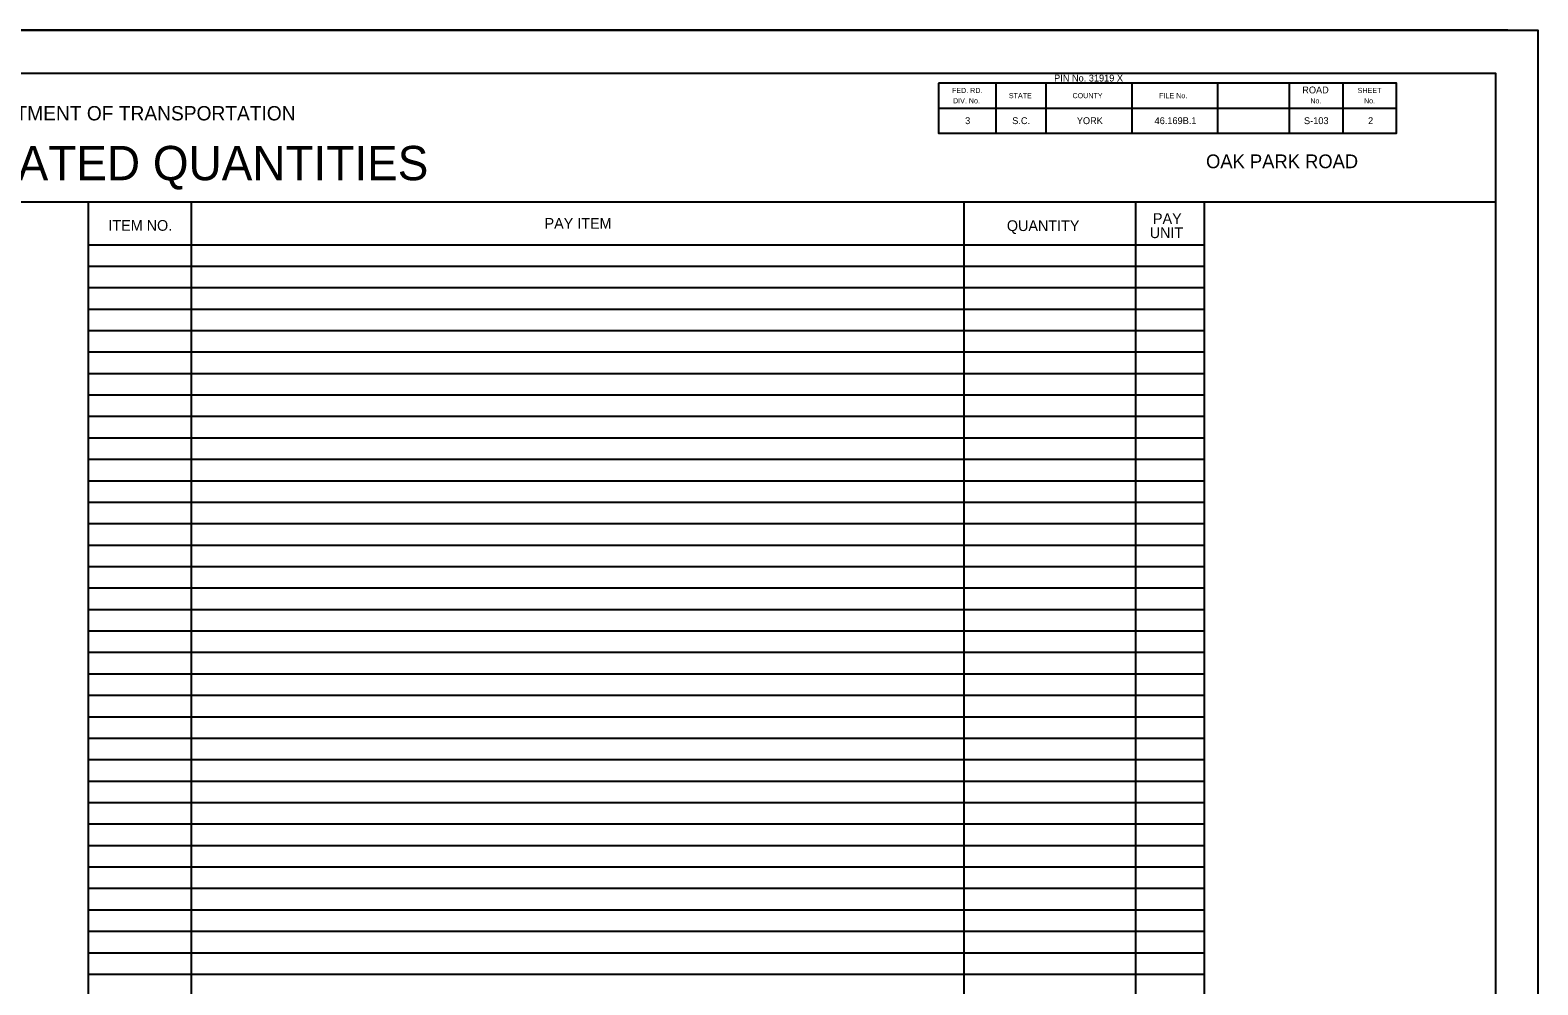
# Model space of a CAD drawing. Extents: x -796 to 2793, y -4650 to 4425.
# Drawn here: x 1899 to 2777, y -706 to -150 of the extents above; entities that cross this region are included whole.
import ezdxf

# ---------------------------------------------------------------- set-up
doc = ezdxf.new("R2010")
doc.units = 0
for name, color, linetype in [('RD_HC_CL', 7, 'Continuous'), ('RD_HC_Data', 7, 'Continuous'), ('RD_HC_Data_Tic', 7, 'Continuous')]:
    doc.layers.add(name, color=color, linetype=linetype)

msp = doc.modelspace()

# ---------------------------------------------------------------- linework, layer by layer
at = {"layer": 'RD_HC_CL'}
msp.add_lwpolyline([(981.41, -150), (2777.4, -150), (2777.4, -1250), (981.41, -1250)], close=True, dxfattribs=at)
at = {"layer": 'RD_HC_Data'}
for p, q in [((2760, -150), (1000, -150)), ((2760, -150), (1000, -150)), ((1915.25, -175), (1915.25, -174.95)), ((2752.75, -175), (2752.75, -242.85)), ((2461.65, -180.85), (2461.65, -195.45)), ((2490.85, -180.85), (2490.85, -195.45)), ((2540.85, -180.85), (2540.85, -195.45)), ((2590.85, -180.85), (2590.85, -195.45)), ((2632.5, -180.85), (2632.5, -195.45)), ((2663.75, -180.85), (2663.75, -195.45)), ((2428.35, -195.45), (2695, -195.45)), ((2461.65, -195.45), (2461.65, -210.05)), ((2490.85, -195.45), (2490.85, -210.05)), ((2540.85, -195.45), (2540.85, -210.05)), ((2590.85, -195.45), (2590.85, -210.05)), ((2632.5, -195.45), (2632.5, -210.05)), ((2663.75, -195.45), (2663.75, -210.05)), ((1627.75, -250), (2752.75, -250)), ((1932.95, -250), (1932.95, -1225)), ((1992.95, -250), (1992.95, -1225)), ((2442.95, -250), (2442.95, -1225)), ((2542.95, -250), (2542.95, -1225)), ((2582.95, -250), (2582.95, -1225)), ((1932.95, -275), (2582.95, -275)), ((1932.95, -287.5), (2582.95, -287.5)), ((1932.95, -300), (2582.95, -300)), ((1932.95, -312.5), (2582.95, -312.5)), ((1932.95, -325), (2582.95, -325)), ((1932.95, -337.5), (2582.95, -337.5)), ((1932.95, -350), (2582.95, -350)), ((1932.95, -362.5), (2582.95, -362.5)), ((1932.95, -375), (2582.95, -375)), ((1932.95, -387.5), (2582.95, -387.5)), ((1932.95, -400), (2582.95, -400)), ((1932.95, -412.5), (2582.95, -412.5)), ((1932.95, -425), (2582.95, -425)), ((1932.95, -437.5), (2582.95, -437.5)), ((1932.95, -450), (2582.95, -450)), ((1932.95, -462.5), (2582.95, -462.5)), ((1932.95, -475), (2582.95, -475)), ((1932.95, -487.5), (2582.95, -487.5)), ((1932.95, -500), (2582.95, -500)), ((1932.95, -512.5), (2582.95, -512.5)), ((1932.95, -525), (2582.95, -525)), ((1932.95, -537.5), (2582.95, -537.5)), ((1932.95, -550), (2582.95, -550)), ((1932.95, -562.5), (2582.95, -562.5)), ((1932.95, -575), (2582.95, -575)), ((1932.95, -587.5), (2582.95, -587.5)), ((1932.95, -600), (2582.95, -600)), ((1932.95, -612.5), (2582.95, -612.5)), ((1932.95, -625), (2582.95, -625)), ((1932.95, -637.5), (2582.95, -637.5)), ((1932.95, -650), (2582.95, -650)), ((1932.95, -662.5), (2582.95, -662.5)), ((1932.95, -675), (2582.95, -675)), ((1932.95, -687.5), (2582.95, -687.5)), ((1932.95, -700), (2582.95, -700))]:
    msp.add_line(p, q, dxfattribs=at)
for points in [[(1077.75, -175), (2752.75, -175), (2752.75, -1225), (1077.75, -1225)], [(2428.35, -180.85), (2428.35, -210.05), (2695, -210.05), (2695, -180.85)]]:
    msp.add_lwpolyline(points, close=True, dxfattribs=at)

# ---------------------------------------------------------------- texts
at = {"layer": 'RD_HC_Data_Tic'}
for s, height, p in [('FED. RD.', 3, (2436.12, -186.65)), ('PIN No. 31919 X   ', 4, (2495.62, -179.93)), ('      ROAD      ', 4, (2631.25, -186.85)), ('SHEET', 3, (2672.46, -186.65)), ('DIV. No.', 3, (2436.74, -192.65)), ('STATE', 3, (2469.27, -189.65)), ('COUNTY', 3, (2506.34, -189.65)), ('FILE No.', 3, (2556.85, -189.65)), ('No.', 3, (2644.88, -192.65)), ('No.', 3, (2676.13, -192.65)), ('SOUTH CAROLINA DEPARTMENT OF TRANSPORTATION', 8.3499, (1749.79, -202.58)), ('3', 4, (2443.8, -204.75)), ('S.C.', 4, (2471.23, -204.75)), ('      YORK      ', 4, (2499.93, -204.75)), ('   46.169B.1    ', 4, (2549.69, -204.75)), ('     S-103     ', 4, (2633.76, -204.75)), ('       2        ', 4, (2668.11, -204.75)), ('SUMMARY OF ESTIMATED QUANTITIES ', 20, (1621.44, -237.45)), ('OAK PARK ROAD                 ', 8, (2584.12, -230.43)), ('ITEM NO.', 6.25, (1944.75, -266.9)), ('PAY ITEM', 6.25, (2198.8, -265.7)), ('QUANTITY', 6.25, (2468.11, -267.05)), ('PAY', 6.25, (2553.21, -262.92)), ('UNIT', 6.25, (2551.32, -271.17))]:
    msp.add_text(s, height=height, dxfattribs=at).set_placement(p)

doc.saveas('drawing.dxf')
